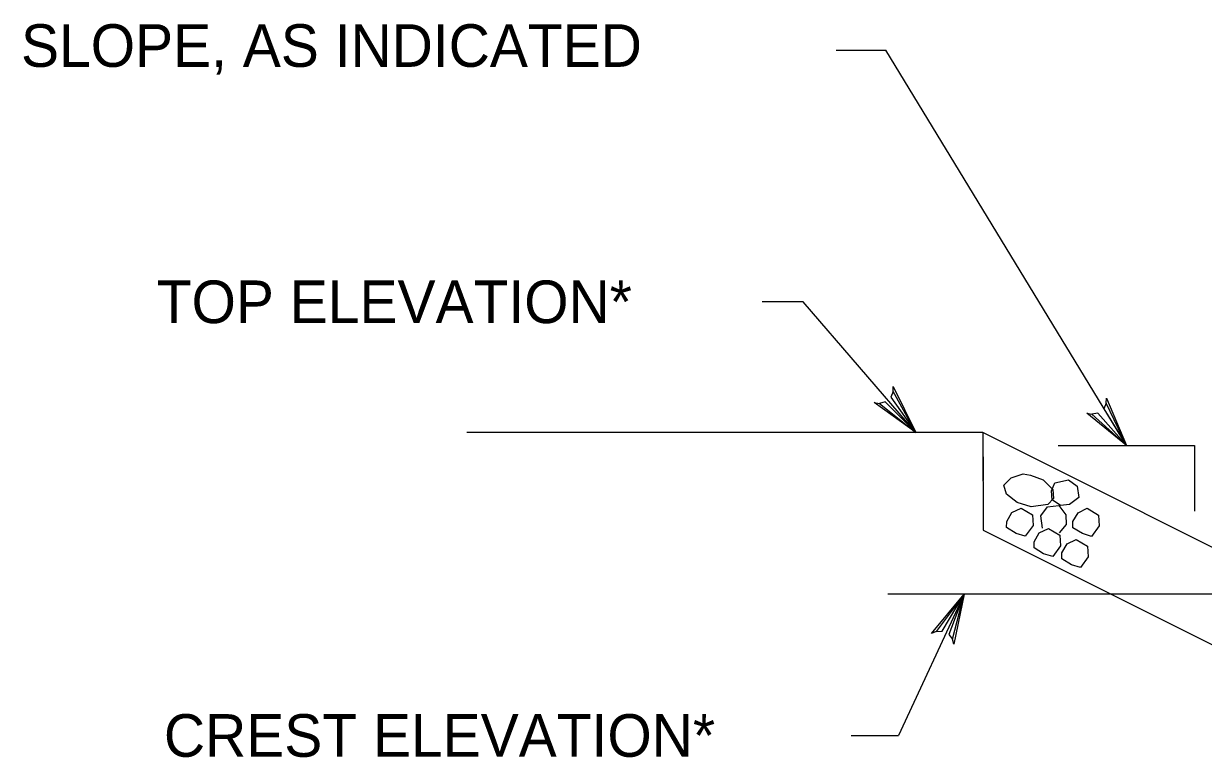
# Model space of a CAD drawing. Extents: x 636462 to 639890, y 299944 to 300538.
# Drawn here: x 637800.7 to 637883.7, y 300154.8 to 300206.4 of the extents above; entities that cross this region are included whole.
import ezdxf

# ---------------------------------------------------------------- set-up
doc = ezdxf.new("R2010")
doc.units = 0
doc.layers.add('Default', color=7, linetype='Continuous')

msp = doc.modelspace()

# ---------------------------------------------------------------- linework, layer by layer
at = {"layer": 'Default'}
for p, q in [((637857.868, 300204.553), (637861.365, 300204.553)), ((637878.276, 300176.757), (637861.365, 300204.553)), ((637855.553, 300186.868), (637852.657, 300186.868)), ((637863.459, 300177.678), (637855.553, 300186.868)), ((637868.19, 300177.678), (637831.886, 300177.678)), ((637868.19, 300177.678), (637868.2, 300170.823)), ((637873.475, 300176.757), (637883.078, 300176.757)), ((637883.078, 300176.757), (637883.078, 300172.14)), ((637869.665, 300173.976), (637870.174, 300174.494)), ((637870.174, 300174.494), (637871.018, 300174.765)), ((637871.018, 300174.765), (637871.538, 300174.681)), ((637871.538, 300174.681), (637872.418, 300174.349)), ((637872.418, 300174.349), (637873.101, 300173.678)), ((637873.256, 300174.144), (637874.196, 300174.359)), ((637874.196, 300174.359), (637874.818, 300173.918)), ((637869.849, 300173.338), (637869.665, 300173.976)), ((637870.588, 300172.765), (637869.849, 300173.338)), ((637873.019, 300173.584), (637873.256, 300174.144)), ((637873.054, 300172.955), (637873.019, 300173.584)), ((637873.101, 300173.678), (637873.16, 300173.049)), ((637874.818, 300173.918), (637874.941, 300173.109)), ((637871.569, 300172.451), (637870.588, 300172.765)), ((637872.757, 300172.624), (637871.569, 300172.451)), ((637872.721, 300172.451), (637873.528, 300172.549)), ((637873.16, 300173.049), (637872.757, 300172.624)), ((637873.653, 300172.541), (637873.054, 300172.955)), ((637873.528, 300172.549), (637874.011, 300171.892)), ((637874.284, 300172.625), (637873.653, 300172.541)), ((637874.941, 300173.109), (637874.284, 300172.625)), ((637869.86, 300171.426), (637870.226, 300172.054)), ((637870.226, 300172.054), (637870.872, 300172.362)), ((637870.872, 300172.362), (637871.667, 300171.885)), ((637871.667, 300171.885), (637871.718, 300171.131)), ((637872.255, 300171.83), (637872.721, 300172.451)), ((637872.373, 300170.947), (637872.255, 300171.83)), ((637874.011, 300171.892), (637874.042, 300171.214)), ((637874.513, 300171.413), (637874.879, 300172.04)), ((637874.879, 300172.04), (637875.525, 300172.349)), ((637875.525, 300172.349), (637876.32, 300171.872)), ((637876.32, 300171.872), (637876.372, 300171.117)), ((637869.857, 300171.001), (637869.86, 300171.426)), ((637870.531, 300170.582), (637869.857, 300171.001)), ((637871.718, 300171.131), (637871.17, 300170.39)), ((637872.154, 300170.629), (637872.8, 300170.938)), ((637872.8, 300170.938), (637873.595, 300170.46)), ((637874.042, 300171.214), (637873.553, 300170.62)), ((637874.511, 300170.988), (637874.513, 300171.413)), ((637875.184, 300170.568), (637874.511, 300170.988)), ((637876.372, 300171.117), (637875.823, 300170.377)), ((637871.17, 300170.39), (637870.531, 300170.582)), ((637871.785, 300169.576), (637871.788, 300170.002)), ((637871.788, 300170.002), (637872.154, 300170.629)), ((637873.595, 300170.46), (637873.646, 300169.706)), ((637874.105, 300169.854), (637874.751, 300170.163)), ((637874.751, 300170.163), (637875.546, 300169.685)), ((637875.823, 300170.377), (637875.184, 300170.568)), ((637872.459, 300169.157), (637871.785, 300169.576)), ((637873.646, 300169.706), (637873.098, 300168.965)), ((637873.736, 300168.801), (637873.739, 300169.227)), ((637873.739, 300169.227), (637874.105, 300169.854)), ((637875.546, 300169.685), (637875.597, 300168.931)), ((637873.098, 300168.965), (637872.459, 300169.157)), ((637874.41, 300168.382), (637873.736, 300168.801)), ((637875.049, 300168.19), (637874.41, 300168.382)), ((637875.597, 300168.931), (637875.049, 300168.19)), ((637889.572, 300166.325), (637861.501, 300166.325)), ((637866.868, 300166.325), (637862.247, 300156.38)), ((637858.933, 300156.38), (637862.247, 300156.38))]:
    msp.add_line(p, q, dxfattribs=at)
for points in [[(637861.867, 300180.562), (637861.865, 300180.911), (637863.459, 300177.678), (637861.867, 300180.562), (637861.708, 300180.171), (637863.459, 300177.678), (637861.311, 300179.83), (637860.907, 300179.727), (637863.459, 300177.678), (637860.531, 300179.78), (637860.907, 300179.727)], [(637876.866, 300179.734), (637876.885, 300180.083), (637878.276, 300176.757), (637876.866, 300179.734), (637876.683, 300179.354), (637878.276, 300176.757), (637876.266, 300179.038), (637875.855, 300178.961), (637878.276, 300176.757), (637875.484, 300179.037), (637875.855, 300178.961)], [(637976.157, 300174.477), (637976.154, 300177.743), (637953.339, 300166.333), (637921.977, 300166.328), (637890.893, 300166.325), (637868.19, 300177.678), (637868.195, 300174.317)], [(637868.2, 300170.823), (637889.671, 300160.087), (637954.366, 300160.092), (637976.159, 300170.987)], [(637864.891, 300163.69), (637864.573, 300163.545), (637866.868, 300166.325), (637864.891, 300163.69), (637865.313, 300163.705), (637866.868, 300166.325), (637865.787, 300163.483), (637866.046, 300163.156), (637866.868, 300166.325), (637866.152, 300162.792), (637866.046, 300163.156)]]:
    msp.add_lwpolyline(points, dxfattribs=at)

# ---------------------------------------------------------------- texts
for s, p in [('SLOPE, AS INDICATED', (637800.539, 300203.385)), ('TOP ELEVATION*', (637810.085, 300185.369)), ('CREST ELEVATION*', (637810.589, 300154.881))]:
    msp.add_text(s, height=2.99804, dxfattribs=at).set_placement(p)

doc.saveas('drawing.dxf')
